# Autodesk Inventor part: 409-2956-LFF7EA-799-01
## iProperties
Created: 2010-11
Part Number: 409-2956-LFF7EA-799-01
Material: 3/4" OD TUBE - SS
Document SubType Name: Modeling
Designer: S. Boerckel
Engineer: Steve Boerckel
Mass: 55.5632 g
Surface Area: 85.1076 cm^2
Volume: 6.87664 cm^3
Density: 8.08 g/cm^3
Description: DRAIN TUBING
User Status: CUT
Length: 3.000 in
SMR: =<MATERIAL>
Author: S. Boerckel
Revision Number: 0
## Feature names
1. Extrusion1
